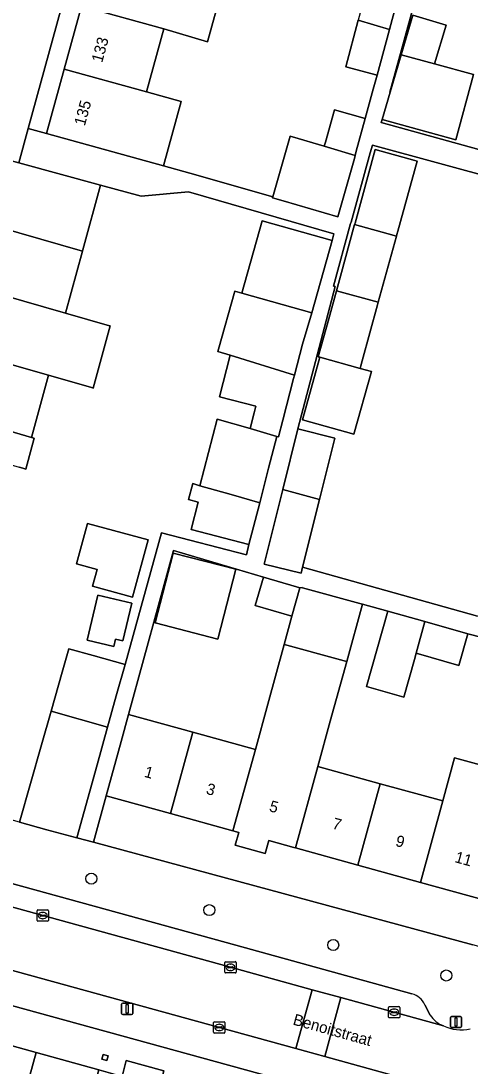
# Model space of a CAD drawing. Extents: x 159817 to 160765, y 380688 to 381638.
# Drawn here: x 160248.8 to 160288.6, y 381017.8 to 381110.3 of the extents above; entities that cross this region are included whole.
import ezdxf

# ---------------------------------------------------------------- set-up
doc = ezdxf.new("R2010")
doc.units = 0
for name, color, linetype in [('IMGEO_Boom', 7, 'Continuous'), ('IMGEO_Erf', 7, 'Continuous'), ('IMGEO_Kolk', 7, 'Continuous'), ('IMGEO_Lichtmast', 7, 'Continuous'), ('IMGEO_Openbare_ruimte_label', 7, 'Continuous'), ('IMGEO_Pand', 7, 'Continuous'), ('IMGEO_Pand_nummerreeks', 7, 'Continuous'), ('IMGEO_Parkeervlak_open', 7, 'Continuous'), ('IMGEO_Rijbaan_lokaal_open', 7, 'Continuous'), ('IMGEO_Voetpad_open', 7, 'Continuous')]:
    doc.layers.add(name, color=color, linetype=linetype)

msp = doc.modelspace()

# ---------------------------------------------------------------- linework, layer by layer
at = {"layer": 'IMGEO_Boom'}
for centre in [(160255.039, 381034.397), (160265.483, 381031.606), (160276.45, 381028.521), (160286.454, 381025.822)]:
    msp.add_circle(centre, 0.489, dxfattribs=at)
at = {"layer": 'IMGEO_Erf'}
for points in [[(160261.794, 381139.428), (160263.319, 381144.997), (160264.844, 381150.565), (160266.354, 381156.08), (160264.775, 381156.514), (160249.46, 381100.752), (160251.081, 381100.307), (160252.639, 381105.997), (160254.167, 381111.576), (160255.692, 381117.147), (160257.217, 381122.713), (160258.712, 381128.174), (160260.267, 381133.853)], [(160282.049, 381091.247), (160280.442, 381085.394), (160280.376, 381085.155), (160279.015, 381080.2), (160278.893, 381079.757), (160278.834, 381079.541), (160279.84, 381079.265), (160278.289, 381073.714), (160273.727, 381074.989), (160275.272, 381080.52), (160275.13, 381080.559), (160276.052, 381083.917), (160276.738, 381086.411), (160276.822, 381086.72), (160277.091, 381087.698), (160278.345, 381092.264), (160278.381, 381092.394), (160280.166, 381098.89), (160283.682, 381097.924), (160283.869, 381097.872), (160282.166, 381091.672), (160282.085, 381091.377)], [(160260.059, 381064.358), (160258.681, 381059.305), (160255.157, 381060.266), (160255.563, 381061.754), (160253.733, 381062.253), (160254.705, 381065.819)], [(160272.11, 381055.116), (160272.797, 381057.615), (160269.55, 381058.573), (160270.289, 381061.073), (160262.318, 381063.43), (160258.33, 381048.907), (160264.026, 381047.342), (160269.557, 381045.823), (160270.659, 381049.834)], [(160260.686, 381057.015), (160262.28, 381063.196), (160267.842, 381061.762), (160266.248, 381055.581)], [(160255.621, 381059.477), (160258.628, 381058.765), (160257.84, 381055.433), (160257.179, 381055.589), (160257.021, 381054.922), (160254.675, 381055.477)], [(160227.232, 381028.872), (160226.692, 381026.933), (160226.99, 381026.85), (160226.934, 381026.648), (160226.618, 381025.501), (160228.603, 381024.952), (160228.843, 381025.82), (160231.638, 381025.048), (160231.399, 381024.18), (160233.394, 381023.629), (160233.534, 381023.59), (160239.074, 381022.06), (160244.613, 381020.53), (160250.152, 381019), (160255.691, 381017.47), (160257.76, 381016.898), (160258.136, 381018.297), (160261.462, 381017.376), (160261.076, 381015.982), (160261.232, 381015.939), (160266.771, 381014.409), (160272.48, 381012.832), (160273.402, 381016.188)], [(160256.525, 381018.729), (160256.408, 381018.306), (160255.983, 381018.424), (160256.1, 381018.847)]]:
    msp.add_lwpolyline(points, close=True, dxfattribs=at)
for points in [[(160266.858, 381113.99), (160265.329, 381108.426), (160261.452, 381109.574), (160259.919, 381103.997), (160262.994, 381103.152), (160261.431, 381097.463), (160263.771, 381096.82), (160271.103, 381094.713), (160272.65, 381100.095), (160272.857, 381100.033), (160275.656, 381099.199), (160275.753, 381099.539), (160276.573, 381102.41), (160279.29, 381101.633), (160279.999, 381104.231), (160280.334, 381105.481), (160277.563, 381106.222), (160278.668, 381110.352)], [(160284.075, 381113.535), (160281.465, 381103.982), (160281.49, 381103.975), (160282.468, 381107.283), (160283.5, 381110.775), (160286.436, 381109.907), (160285.421, 381106.472), (160288.873, 381105.524), (160287.297, 381099.762), (160280.774, 381101.554), (160280.693, 381101.28), (160299.698, 381096.057), (160301.355, 381102.088), (160302.972, 381107.97), (160303.854, 381111.18)], [(160309.076, 381091.342), (160279.912, 381099.299), (160279.723, 381098.611), (160278.041, 381092.488), (160277.983, 381092.364), (160276.46, 381086.819), (160276.634, 381086.771), (160273.322, 381074.184), (160276.594, 381073.366), (160275.238, 381067.942), (160273.739, 381061.948), (160289.226, 381057.613)], [(160248.67, 381039.377), (160250.62, 381046.217), (160251.474, 381049.214), (160252.457, 381052.661), (160253.047, 381054.732), (160255.204, 381054.13), (160258.02, 381053.345), (160261.265, 381064.985), (160268.76, 381063.052), (160268.992, 381063.951), (160263.869, 381065.283), (160264.497, 381067.702), (160263.649, 381067.936), (160264.018, 381069.345), (160264.647, 381069.157), (160266.164, 381075.042), (160269.085, 381074.206), (160269.446, 381075.606), (160269.595, 381076.183), (160266.371, 381077.015), (160267.322, 381080.702), (160266.236, 381081.037), (160266.291, 381081.233), (160267.734, 381086.368), (160268.358, 381086.193), (160270.157, 381092.595), (160276.345, 381090.857), (160276.516, 381091.447), (160263.639, 381095.169), (160259.465, 381094.766), (160255.861, 381095.751), (160254.297, 381090.031), (160254.266, 381089.918), (160252.757, 381084.421), (160256.641, 381083.308), (160256.698, 381083.291), (160255.19, 381077.798), (160255.132, 381077.815), (160255.042, 381077.84), (160251.248, 381078.926), (160249.738, 381073.428), (160249.98, 381073.359), (160249.232, 381070.635), (160248.99, 381070.704), (160248.665, 381070.797)], [(160292.047, 381055.105), (160288.356, 381056.055), (160287.566, 381053.262), (160283.783, 381054.332), (160283.633, 381053.784), (160282.687, 381050.444), (160279.382, 381051.38), (160281.274, 381058.06), (160279.036, 381058.675), (160277.642, 381053.601), (160276.19, 381048.315), (160275.088, 381044.304), (160280.618, 381042.784), (160286.148, 381041.265), (160287.195, 381045.079), (160292.895, 381043.513)], [(160289.87, 381032.5), (160284.171, 381034.065), (160278.641, 381035.584), (160273.11, 381037.104), (160272.957, 381037.146), (160270.739, 381037.755), (160270.427, 381036.619), (160267.775, 381037.347), (160268.087, 381038.483), (160267.579, 381038.623), (160262.049, 381040.142), (160256.352, 381041.707), (160255.246, 381037.612), (160288.809, 381028.544)]]:
    msp.add_lwpolyline(points, dxfattribs=at)
at = {"layer": 'IMGEO_Kolk'}
for p, q in [((160250.236, 381030.699), (160250.236, 381031.551)), ((160250.311, 381031.625), (160251.163, 381031.625)), ((160251.237, 381031.551), (160251.237, 381030.699)), ((160251.163, 381030.625), (160250.311, 381030.625)), ((160250.495, 381031.119), (160250.495, 381031.131)), ((160250.933, 381031.082), (160250.535, 381031.082)), ((160250.538, 381031.168), (160250.936, 381031.168)), ((160250.747, 381030.845), (160250.722, 381030.845)), ((160250.724, 381031.405), (160250.749, 381031.405)), ((160250.979, 381031.131), (160250.979, 381031.119)), ((160266.849, 381026.121), (160266.849, 381026.973)), ((160266.924, 381027.047), (160267.776, 381027.047)), ((160267.337, 381026.827), (160267.362, 381026.827)), ((160267.85, 381026.973), (160267.85, 381026.121)), ((160267.776, 381026.047), (160266.924, 381026.047)), ((160267.108, 381026.541), (160267.108, 381026.553)), ((160267.546, 381026.504), (160267.148, 381026.504)), ((160267.151, 381026.59), (160267.549, 381026.59)), ((160267.36, 381026.267), (160267.335, 381026.267)), ((160267.592, 381026.553), (160267.592, 381026.541)), ((160281.339, 381022.15), (160281.339, 381023.002)), ((160281.414, 381023.076), (160282.266, 381023.076)), ((160281.598, 381022.57), (160281.598, 381022.582)), ((160282.036, 381022.533), (160281.638, 381022.533)), ((160281.641, 381022.619), (160282.039, 381022.619)), ((160281.85, 381022.296), (160281.825, 381022.296)), ((160281.827, 381022.856), (160281.852, 381022.856)), ((160282.082, 381022.582), (160282.082, 381022.57)), ((160282.34, 381023.002), (160282.34, 381022.15)), ((160265.867, 381020.8), (160265.867, 381021.652)), ((160265.942, 381021.726), (160266.794, 381021.726)), ((160266.169, 381021.269), (160266.567, 381021.269)), ((160266.355, 381021.506), (160266.38, 381021.506)), ((160266.868, 381021.652), (160266.868, 381020.8)), ((160282.266, 381022.076), (160281.414, 381022.076)), ((160266.794, 381020.726), (160265.942, 381020.726)), ((160266.126, 381021.22), (160266.126, 381021.232)), ((160266.564, 381021.183), (160266.166, 381021.183)), ((160266.378, 381020.946), (160266.353, 381020.946)), ((160266.61, 381021.232), (160266.61, 381021.22))]:
    msp.add_line(p, q, dxfattribs=at)
for points in [[(160250.236, 381030.699), (160250.236, 381031.551)], [(160250.311, 381031.625), (160251.163, 381031.625)], [(160251.237, 381031.551), (160251.237, 381030.699)], [(160251.163, 381030.625), (160250.311, 381030.625)], [(160266.849, 381026.121), (160266.849, 381026.973)], [(160266.924, 381027.047), (160267.776, 381027.047)], [(160267.85, 381026.973), (160267.85, 381026.121)], [(160267.776, 381026.047), (160266.924, 381026.047)], [(160281.339, 381022.15), (160281.339, 381023.002)], [(160281.414, 381023.076), (160282.266, 381023.076)], [(160282.34, 381023.002), (160282.34, 381022.15)], [(160265.867, 381020.8), (160265.867, 381021.652)], [(160265.942, 381021.726), (160266.794, 381021.726)], [(160266.868, 381021.652), (160266.868, 381020.8)], [(160282.266, 381022.076), (160281.414, 381022.076)], [(160266.794, 381020.726), (160265.942, 381020.726)]]:
    msp.add_lwpolyline(points, dxfattribs=at)
for centre, radius, start, end in [((160250.313, 381031.549), 0.0765, 91.55205, 178.44795), ((160250.313, 381031.549), 0.0765, 91.55205, 178.44795), ((160251.161, 381031.549), 0.0765, 1.55205, 88.44795), ((160251.161, 381031.549), 0.0765, 1.55205, 88.44795), ((160250.313, 381030.701), 0.0765, 181.55205, 268.44795), ((160250.313, 381030.701), 0.0765, 181.55205, 268.44795), ((160250.535, 381031.128), 0.0403, 85.87752, 175.75265), ((160250.532, 381031.118), 0.0366, 178.93798, 274.71019), ((160250.936, 381031.125), 0.043, 264.86636, 352.45326), ((160250.94, 381031.13), 0.0386, 1.73085, 96.63898), ((160251.161, 381030.701), 0.0765, 271.55205, 358.44795), ((160251.161, 381030.701), 0.0765, 271.55205, 358.44795), ((160266.926, 381026.971), 0.0765, 91.55205, 178.44795), ((160266.926, 381026.971), 0.0765, 91.55205, 178.44795), ((160267.774, 381026.971), 0.0765, 1.55205, 88.44795), ((160267.774, 381026.971), 0.0765, 1.55205, 88.44795), ((160266.926, 381026.123), 0.0765, 181.55205, 268.44795), ((160266.926, 381026.123), 0.0765, 181.55205, 268.44795), ((160267.148, 381026.55), 0.0403, 85.87752, 175.75265), ((160267.145, 381026.54), 0.0366, 178.93798, 274.71019), ((160267.549, 381026.547), 0.043, 264.86636, 352.45326), ((160267.553, 381026.552), 0.0386, 1.73085, 96.63898), ((160267.774, 381026.123), 0.0765, 271.55205, 358.44795), ((160267.774, 381026.123), 0.0765, 271.55205, 358.44795), ((160281.416, 381023), 0.0765, 91.55205, 178.44795), ((160281.416, 381023), 0.0765, 91.55205, 178.44795), ((160281.638, 381022.579), 0.0403, 85.87752, 175.75265), ((160281.635, 381022.569), 0.0366, 178.93798, 274.71019), ((160282.039, 381022.576), 0.043, 264.86636, 352.45326), ((160282.043, 381022.581), 0.0386, 1.73085, 96.63898), ((160282.264, 381023), 0.0765, 1.55205, 88.44795), ((160282.264, 381023), 0.0765, 1.55205, 88.44795), ((160265.944, 381021.65), 0.0765, 91.55205, 178.44795), ((160265.944, 381021.65), 0.0765, 91.55205, 178.44795), ((160266.166, 381021.229), 0.0403, 85.87752, 175.75265), ((160266.571, 381021.231), 0.0386, 1.73085, 96.63898), ((160266.792, 381021.65), 0.0765, 1.55205, 88.44795), ((160266.792, 381021.65), 0.0765, 1.55205, 88.44795), ((160281.416, 381022.152), 0.0765, 181.55205, 268.44795), ((160281.416, 381022.152), 0.0765, 181.55205, 268.44795), ((160282.264, 381022.152), 0.0765, 271.55205, 358.44795), ((160282.264, 381022.152), 0.0765, 271.55205, 358.44795), ((160265.944, 381020.802), 0.0765, 181.55205, 268.44795), ((160265.944, 381020.802), 0.0765, 181.55205, 268.44795), ((160266.163, 381021.219), 0.0366, 178.93798, 274.71019), ((160266.567, 381021.226), 0.043, 264.86636, 352.45326), ((160266.792, 381020.802), 0.0765, 271.55205, 358.44795), ((160266.792, 381020.802), 0.0765, 271.55205, 358.44795)]:
    msp.add_arc(centre, radius, start, end, dxfattribs=at)
for centre, major_axis, ratio, start_param, end_param in [((160250.723, 381031.125), (-0.387, 0.002), 0.722429, 4.712389, 7.853982), ((160250.748, 381031.125), (-0.39, 0.002), 0.717154, 1.570796, 4.712389), ((160267.336, 381026.547), (-0.387, 0.002), 0.722429, 4.712389, 7.853982), ((160267.361, 381026.547), (-0.39, 0.002), 0.717154, 1.570796, 4.712389), ((160281.826, 381022.576), (-0.387, 0.002), 0.722429, 4.712389, 7.853982), ((160281.851, 381022.576), (-0.39, 0.002), 0.717154, 1.570796, 4.712389), ((160266.354, 381021.226), (-0.387, 0.002), 0.722429, 4.712389, 7.853982), ((160266.379, 381021.226), (-0.39, 0.002), 0.717154, 1.570796, 4.712389)]:
    msp.add_ellipse(centre, major_axis=major_axis, ratio=ratio, start_param=start_param, end_param=end_param, dxfattribs=at)
at = {"layer": 'IMGEO_Lichtmast'}
for p, q in [((160257.716, 381022.473), (160257.716, 381023.273)), ((160257.716, 381023.273), (160257.716, 381022.473)), ((160257.816, 381023.373), (160258.606, 381023.373)), ((160258.606, 381023.373), (160257.816, 381023.373)), ((160258.706, 381023.273), (160258.706, 381022.473)), ((160258.706, 381022.473), (160258.706, 381023.273)), ((160258.606, 381022.373), (160257.816, 381022.373)), ((160257.816, 381022.373), (160258.606, 381022.373)), ((160286.923, 381022.209), (160287.713, 381022.209)), ((160287.713, 381022.209), (160286.923, 381022.209)), ((160286.823, 381021.309), (160286.823, 381022.109)), ((160286.823, 381022.109), (160286.823, 381021.309)), ((160287.813, 381022.109), (160287.813, 381021.309)), ((160287.813, 381021.309), (160287.813, 381022.109)), ((160287.713, 381021.209), (160286.923, 381021.209)), ((160286.923, 381021.209), (160287.713, 381021.209))]:
    msp.add_line(p, q, dxfattribs=at)
for points in [[(160258.136, 381023.248), (160258.286, 381023.248), (160258.286, 381022.498), (160258.136, 381022.498), (160258.136, 381023.248)], [(160287.243, 381022.084), (160287.393, 381022.084), (160287.393, 381021.334), (160287.243, 381021.334), (160287.243, 381022.084)]]:
    msp.add_lwpolyline(points, dxfattribs=at)
for centre, start, end in [((160257.816, 381023.273), 90, 180), ((160257.816, 381023.273), 90, 180), ((160258.606, 381023.273), 0, 90), ((160258.606, 381023.273), 360, 90), ((160257.816, 381022.473), 180, 270), ((160257.816, 381022.473), 180, 270), ((160258.606, 381022.473), 270, 0), ((160258.606, 381022.473), 270, 0), ((160286.923, 381022.109), 90, 180), ((160286.923, 381022.109), 90, 180), ((160287.713, 381022.109), 0, 90), ((160287.713, 381022.109), 360, 90), ((160286.923, 381021.309), 180, 270), ((160286.923, 381021.309), 180, 270), ((160287.713, 381021.309), 270, 0), ((160287.713, 381021.309), 270, 0)]:
    msp.add_arc(centre, 0.1, start, end, dxfattribs=at)
at = {"layer": 'IMGEO_Pand'}
for points in [[(160254.167, 381111.576), (160261.452, 381109.574), (160265.329, 381108.426), (160266.858, 381113.99), (160266.114, 381114.212), (160255.692, 381117.147)], [(160281.418, 381109.532), (160282.427, 381113.302), (160279.656, 381114.043), (160278.668, 381110.352)], [(160254.167, 381111.576), (160252.639, 381105.997), (160259.919, 381103.997), (160261.452, 381109.574)], [(160281.418, 381109.532), (160278.668, 381110.352), (160277.563, 381106.222), (160280.334, 381105.481)], [(160282.468, 381107.283), (160285.421, 381106.472), (160286.436, 381109.907), (160283.5, 381110.775)], [(160285.421, 381106.472), (160282.468, 381107.283), (160281.49, 381103.975), (160281.136, 381102.779), (160280.774, 381101.554), (160287.297, 381099.762), (160288.873, 381105.524)], [(160259.919, 381103.997), (160252.639, 381105.997), (160251.081, 381100.307), (160261.431, 381097.463), (160262.994, 381103.152)], [(160279.29, 381101.633), (160276.573, 381102.41), (160275.753, 381099.539), (160275.656, 381099.199), (160278.405, 381098.381), (160278.47, 381098.763)], [(160278.329, 381098.116), (160278.405, 381098.381), (160275.656, 381099.199), (160272.857, 381100.033), (160272.65, 381100.095), (160271.103, 381094.713), (160271.076, 381094.617), (160271.284, 381094.558), (160272.007, 381094.35), (160276.846, 381092.959)], [(160254.266, 381089.918), (160254.297, 381090.031), (160255.861, 381095.751), (160248.629, 381097.728), (160244.527, 381098.85), (160242.964, 381093.156)], [(160278.345, 381092.264), (160281.84, 381091.304), (160282.049, 381091.247), (160282.085, 381091.377), (160282.166, 381091.672), (160283.869, 381097.872), (160283.682, 381097.924), (160280.166, 381098.89), (160278.381, 381092.394)], [(160252.757, 381084.421), (160254.266, 381089.918), (160242.964, 381093.156), (160241.455, 381087.66)], [(160276.345, 381090.857), (160270.157, 381092.595), (160268.358, 381086.193), (160274.547, 381084.455)], [(160282.049, 381091.247), (160281.84, 381091.304), (160278.345, 381092.264), (160277.091, 381087.698), (160276.822, 381086.72), (160276.738, 381086.411), (160280.442, 381085.394)], [(160252.757, 381084.421), (160241.455, 381087.66), (160239.945, 381082.16), (160251.248, 381078.926), (160255.042, 381077.84), (160255.132, 381077.815), (160255.19, 381077.798), (160256.698, 381083.291), (160256.641, 381083.308)], [(160273.736, 381081.693), (160274.547, 381084.455), (160268.358, 381086.193), (160267.734, 381086.368), (160266.291, 381081.233), (160266.236, 381081.037), (160267.322, 381080.702), (160273.027, 381078.942)], [(160280.442, 381085.394), (160276.738, 381086.411), (160276.052, 381083.917), (160275.13, 381080.559), (160275.272, 381080.52), (160278.834, 381079.541), (160278.893, 381079.757), (160279.015, 381080.2), (160280.376, 381085.155)], [(160238.436, 381076.666), (160245.895, 381074.529), (160249.738, 381073.428), (160251.248, 381078.926), (160239.945, 381082.16)], [(160272.948, 381078.636), (160273.027, 381078.942), (160267.322, 381080.702), (160266.371, 381077.015), (160269.595, 381076.183), (160269.446, 381075.606), (160269.085, 381074.206), (160271.459, 381073.525), (160271.618, 381073.48), (160271.997, 381074.948)], [(160278.834, 381079.541), (160275.272, 381080.52), (160273.727, 381074.989), (160278.289, 381073.714), (160279.84, 381079.265)], [(160249.98, 381073.359), (160249.738, 381073.428), (160245.895, 381074.529), (160238.436, 381076.666), (160236.927, 381071.169), (160244.385, 381069.031), (160245.147, 381071.805), (160248.665, 381070.797), (160248.99, 381070.704), (160249.232, 381070.635)], [(160270.73, 381070.695), (160271.459, 381073.525), (160269.085, 381074.206), (160266.164, 381075.042), (160264.647, 381069.157), (160267.409, 381068.365), (160269.943, 381067.639)], [(160271.985, 381068.835), (160275.238, 381067.942), (160276.594, 381073.366), (160273.322, 381074.184)], [(160269.943, 381067.639), (160267.409, 381068.365), (160264.647, 381069.157), (160264.018, 381069.345), (160263.649, 381067.936), (160264.497, 381067.702), (160263.869, 381065.283), (160268.992, 381063.951)], [(160275.238, 381067.942), (160271.985, 381068.835), (160270.332, 381062.225), (160273.604, 381061.407), (160273.739, 381061.948)], [(160260.059, 381064.358), (160254.705, 381065.819), (160253.733, 381062.253), (160255.563, 381061.754), (160255.157, 381060.266), (160258.681, 381059.305)], [(160260.686, 381057.015), (160266.248, 381055.581), (160267.842, 381061.762), (160262.28, 381063.196)], [(160273.487, 381060.127), (160273.201, 381060.212), (160270.289, 381061.073), (160269.55, 381058.573), (160272.797, 381057.615)], [(160279.036, 381058.675), (160278.806, 381058.738), (160273.741, 381060.126), (160273.703, 381060.137), (160273.487, 381060.127), (160272.797, 381057.615), (160272.11, 381055.116), (160272.351, 381055.05), (160276.78, 381053.837), (160277.415, 381053.663), (160277.642, 381053.601)], [(160255.621, 381059.477), (160254.675, 381055.477), (160257.021, 381054.922), (160257.179, 381055.589), (160257.84, 381055.433), (160258.628, 381058.765)], [(160283.783, 381054.332), (160284.552, 381057.132), (160281.274, 381058.06), (160279.382, 381051.38), (160282.687, 381050.444), (160283.633, 381053.784)], [(160288.356, 381056.055), (160284.552, 381057.132), (160283.783, 381054.332), (160287.566, 381053.262)], [(160258.02, 381053.345), (160255.204, 381054.13), (160253.047, 381054.732), (160252.457, 381052.661), (160251.474, 381049.214), (160256.469, 381047.783), (160257.249, 381050.579)], [(160275.088, 381044.304), (160276.19, 381048.315), (160277.642, 381053.601), (160277.415, 381053.663), (160276.78, 381053.837), (160272.351, 381055.05), (160272.11, 381055.116), (160270.659, 381049.834), (160269.557, 381045.823), (160267.579, 381038.623), (160268.087, 381038.483), (160267.775, 381037.347), (160270.427, 381036.619), (160270.739, 381037.755), (160272.957, 381037.146), (160273.11, 381037.104)], [(160256.469, 381047.783), (160251.474, 381049.214), (160250.62, 381046.217), (160248.67, 381039.377), (160251.114, 381038.722), (160253.745, 381038.017), (160255.546, 381044.474)], [(160262.049, 381040.142), (160264.026, 381047.342), (160258.33, 381048.907), (160257.677, 381046.529), (160256.352, 381041.707)], [(160262.049, 381040.142), (160267.579, 381038.623), (160269.557, 381045.823), (160264.026, 381047.342)], [(160291.848, 381039.7), (160292.895, 381043.513), (160287.195, 381045.079), (160286.148, 381041.265), (160284.171, 381034.065), (160289.87, 381032.5)], [(160273.11, 381037.104), (160278.641, 381035.584), (160280.618, 381042.784), (160275.088, 381044.304)], [(160286.148, 381041.265), (160280.618, 381042.784), (160278.641, 381035.584), (160284.171, 381034.065)], [(160244.613, 381020.53), (160241.779, 381010.271), (160244.409, 381009.544), (160245.233, 381012.527), (160248.143, 381011.723), (160250.152, 381019)], [(160255.691, 381017.47), (160250.152, 381019), (160248.143, 381011.723), (160247.383, 381008.968), (160252.921, 381007.438), (160253.682, 381010.193)], [(160256.525, 381018.729), (160256.1, 381018.847), (160255.983, 381018.424), (160256.408, 381018.306)], [(160261.232, 381015.939), (160261.076, 381015.982), (160261.462, 381017.376), (160258.136, 381018.297), (160257.76, 381016.898), (160255.691, 381017.47), (160253.682, 381010.193), (160252.921, 381007.438), (160252.565, 381006.15), (160258.105, 381004.62), (160259.222, 381008.663)]]:
    msp.add_lwpolyline(points, close=True, dxfattribs=at)
at = {"layer": 'IMGEO_Parkeervlak_open'}
for points in [[(160283.414, 381024.197), (160267.84, 381028.499), (160231.031, 381038.636)], [(160227.523, 381037.52), (160228.538, 381037.24), (160231.237, 381036.497), (160267.35, 381026.546), (160274.572, 381024.566), (160277.137, 381023.863), (160286.218, 381021.373)], [(160285.031, 381022.315), (160284.549, 381023.241)]]:
    msp.add_lwpolyline(points, dxfattribs=at)
for centre, radius, start, end in [((160283.058, 381022.622), 1.615, 22.5332, 77.25255), ((160287.002, 381023.58), 2.343, 212.69358, 250.43558)]:
    msp.add_arc(centre, radius, start, end, dxfattribs=at)
at = {"layer": 'IMGEO_Rijbaan_lokaal_open'}
for points in [[(160231.237, 381036.497), (160229.825, 381031.293), (160266.372, 381021.226), (160273.143, 381019.356), (160274.572, 381024.566), (160267.35, 381026.546)], [(160274.572, 381024.566), (160273.143, 381019.356), (160275.707, 381018.648), (160277.137, 381023.863)]]:
    msp.add_lwpolyline(points, close=True, dxfattribs=at)
msp.add_lwpolyline([(160286.218, 381021.373), (160277.137, 381023.863), (160275.707, 381018.648), (160310.756, 381008.967), (160312.174, 381014.237), (160303.571, 381016.59)], dxfattribs=at)
msp.add_arc((160287.771, 381024.543), 3.53, 243.89899, 283.03527, dxfattribs=at)
at = {"layer": 'IMGEO_Voetpad_open'}
for points in [[(160237.726, 381100.461), (160243.082, 381099.217), (160244.527, 381098.85), (160248.629, 381097.728), (160249.46, 381100.752), (160264.775, 381156.514), (160265.047, 381157.506), (160264.876, 381157.554), (160264.96, 381157.861), (160274.082, 381191.318)], [(160282.427, 381113.302), (160281.418, 381109.532), (160280.334, 381105.481), (160279.999, 381104.231), (160279.29, 381101.633), (160278.47, 381098.763), (160278.405, 381098.381), (160278.329, 381098.116), (160276.846, 381092.959), (160272.007, 381094.35), (160271.284, 381094.558), (160271.076, 381094.617), (160271.103, 381094.713), (160263.771, 381096.82), (160261.431, 381097.463), (160251.081, 381100.307), (160249.46, 381100.752), (160248.629, 381097.728), (160255.861, 381095.751), (160259.465, 381094.766), (160263.639, 381095.169), (160276.516, 381091.447), (160276.345, 381090.857), (160274.547, 381084.455), (160273.736, 381081.693), (160273.027, 381078.942), (160272.948, 381078.636), (160271.997, 381074.948), (160271.618, 381073.48), (160271.459, 381073.525), (160270.73, 381070.695), (160269.943, 381067.639), (160268.992, 381063.951), (160268.76, 381063.052), (160261.265, 381064.985), (160258.02, 381053.345), (160257.249, 381050.579), (160256.469, 381047.783), (160255.546, 381044.474), (160253.745, 381038.017), (160255.246, 381037.612), (160256.352, 381041.707), (160257.677, 381046.529), (160258.33, 381048.907), (160262.318, 381063.43), (160270.289, 381061.073), (160273.201, 381060.212), (160273.487, 381060.127), (160273.703, 381060.137), (160273.741, 381060.126), (160278.806, 381058.738), (160279.036, 381058.675), (160281.274, 381058.06), (160284.552, 381057.132), (160288.356, 381056.055), (160292.047, 381055.105)], [(160299.698, 381096.057), (160280.693, 381101.28), (160280.774, 381101.554), (160281.136, 381102.779), (160281.49, 381103.975), (160281.465, 381103.982), (160284.075, 381113.535)], [(160289.226, 381057.613), (160273.739, 381061.948), (160273.604, 381061.407), (160270.332, 381062.225), (160271.985, 381068.835), (160273.322, 381074.184), (160276.634, 381086.771), (160276.46, 381086.819), (160277.983, 381092.364), (160278.041, 381092.488), (160279.723, 381098.611), (160279.912, 381099.299), (160309.076, 381091.342)], [(160255.246, 381037.612), (160253.745, 381038.017), (160251.114, 381038.722), (160248.67, 381039.377), (160241.403, 381041.448), (160234.014, 381043.469), (160228.201, 381045.025), (160229.395, 381049.375), (160224.144, 381050.794), (160223.795, 381049.526)], [(160217.531, 381036.037), (160208.641, 381040.93), (160203.909, 381043.552), (160203.633, 381043.699), (160201.05, 381044.964), (160200.125, 381041.435), (160201.664, 381040.703), (160201.415, 381039.67), (160201.341, 381039.361), (160200.397, 381036.285), (160203.467, 381035.401), (160225.828, 381029.258), (160227.232, 381028.872), (160273.402, 381016.188), (160276.352, 381015.377), (160309.745, 381006.087), (160312.885, 381005.214), (160331.627, 381000), (160361.208, 380991.958)], [(160231.031, 381038.636), (160267.84, 381028.499), (160283.414, 381024.197)], [(160293.795, 381025.659), (160294.18, 381027.04), (160288.809, 381028.544), (160255.246, 381037.612)], [(160275.707, 381018.648), (160273.143, 381019.356), (160266.372, 381021.226), (160229.825, 381031.293), (160227.123, 381032.026), (160226.15, 381032.29)], [(160284.549, 381023.241), (160285.031, 381022.315)], [(160362.838, 380994.62), (160361.434, 380994.997), (160358.736, 380995.757), (160313.429, 381008.229), (160310.756, 381008.967), (160275.707, 381018.648)]]:
    msp.add_lwpolyline(points, dxfattribs=at)
for centre, radius, start, end in [((160283.058, 381022.622), 1.615, 22.5332, 77.25255), ((160287.002, 381023.58), 2.343, 212.69358, 250.43558), ((160287.771, 381024.543), 3.53, 243.89899, 283.03527)]:
    msp.add_arc(centre, radius, start, end, dxfattribs=at)

# ---------------------------------------------------------------- texts
at = {"layer": 'IMGEO_Openbare_ruimte_label'}
msp.add_text('Benoitstraat', height=1, rotation=344.39307, dxfattribs=at).set_placement((160272.815, 381021.492))
at = {"layer": 'IMGEO_Pand_nummerreeks'}
for s, rotation, p in [('133', 74.63418, (160255.997, 381106.529)), ('135', 74.63348, (160254.46, 381100.935)), ('1', 344.64036, (160259.657, 381043.413)), ('3', 344.64036, (160265.134, 381041.909)), ('5', 344.639, (160270.719, 381040.374)), ('7', 344.64036, (160276.306, 381038.84)), ('9', 344.64036, (160281.893, 381037.305)), ('11', 344.639, (160287.145, 381035.863))]:
    msp.add_text(s, height=1, rotation=rotation, dxfattribs=at).set_placement(p)

doc.saveas('drawing.dxf')
